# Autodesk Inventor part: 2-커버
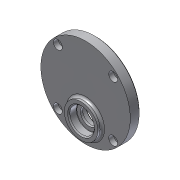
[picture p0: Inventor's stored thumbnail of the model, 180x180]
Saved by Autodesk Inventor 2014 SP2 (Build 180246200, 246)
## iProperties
Created: 2014-12
Part Number: 2-커버
Material: 알루미늄 6061
Document SubType Name: Modeling
Designer: 02
Density: 2.71 g/cm^3
Appearance: 알루미늄 - 평지
Mass: 113.832 g
Surface Area: 145.243 cm^2
Volume: 42.0044 cm^3
Author: 02
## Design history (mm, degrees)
sketch "스케치1"
  geometry: C1 r 40 at (0, 0); 1 further point
  constraints: 1 centre point, 1 coincident
  dimensions: "d0" = 80 diameter of C1
extrude "돌출1" new body sketch "스케치1" distance "d1" = 9; taper "d2" = 0 deg
sketch "스케치2"
  geometry: C1 r 40 at (0, 0) reference; C2 r 15 at (0, -20)
  constraints: 1 centre point, 1 vertical alignment
  dimensions: "d3" = 30 diameter of C2; "d4" = 20 distance of C2.centre C1.centre
extrude "돌출2" join sketch "스케치2" distance "d5" = 4; taper "d6" = 0 deg
sketch "스케치3"
  geometry: L1 (0, -20)-(0, 0); L2 (0, 0)-(0, 11); C1 r 40 at (0, 0) reference; C2 r 14 at (0, 11); C3 r 14 at (0, -20)
  constraints: 4 end point, 2 centre point, 1 collinear, 1 equal radius, 1 vertical
  dimensions: "d7" = 11 distance of L1.end L2.end; "d8" = 20 distance of L1.start L1.end; "d9" = 28 diameter of C2
extrude "돌출3" join sketch "스케치3" distance "d10" = 3; taper "d11" = 0 deg
sketch "스케치4"
  geometry: C1 r 14 at (0, 0) reference; C2 r 11 at (0, 0); 1 further point
  constraints: 1 centre point, 1 coincident
  dimensions: "d12" = 22 diameter of C2
extrude "돌출4" cut sketch "스케치4" distance "d13" = 7; taper "d14" = 0 deg
sketch "스케치5"
  geometry: C1 r 9 at (0, 0); 2 further points
  constraints: 1 centre point, 1 coincident, 1 vertical alignment
  dimensions: "d15" = 18 diameter of C1
extrude "돌출5" cut sketch "스케치5" distance "d16" = 1; taper "d17" = 0 deg
sketch "스케치6"
  geometry: C1 r 14 at (0, 0) reference; C2 r 11 at (0, 0); 1 further point
  constraints: 1 centre point, 1 coincident
  dimensions: "d18" = 22 diameter of C2
extrude "돌출6" cut sketch "스케치6" distance "d19" = 7; taper "d20" = 0 deg
sketch "스케치7"
  geometry: C1 r 15 at (0, 0) reference; C2 r 11 at (0, 0); 1 further point
  constraints: 1 centre point, 1 coincident
  dimensions: "d21" = 22 diameter of C2
extrude "돌출7" cut sketch "스케치7" distance "d22" = 7; taper "d23" = 0 deg
sketch "스케치8"
  geometry: C1 r 11 at (0, 0) reference; C2 r 7.5 at (0, 0); 1 further point
  constraints: 1 centre point, 1 coincident
  dimensions: "d24" = 15 diameter of C2
extrude "돌출8" cut sketch "스케치8" stored distance "d25" = 7; taper "d26" = 0 deg
sketch "스케치9"
  geometry: L1 (0, 0)-(0, 35); L2 (0, 0)-(24.749, 24.749); C1 r 40 at (0, 0) reference; A1 r 35 centre (0, 0) between (0, 35) and (24.749, 24.749)
  constraints: 4 end point, 2 point on circle, 1 centre point, 1 coincident, 1 vertical
  dimensions: "d27" = 70 diameter of A1; "d28" = 45 deg angle of L2 L1
hole "구멍1" sketch "스케치9" at (24.749, 24.749) diameter "d29" = 4.5; stored, may be unused: countersink angle "d33" = 90 deg, drill point angle "d35" = 118 deg; dims "d30" = 6, "d31" = 8, "d32" = 4.4, "d34" = 8
fillet "모깎기1" dims "d39" = 0.3
chamfer "모따기1" distance "d40" = 1; stored, may be unused: second distance "d41" = 2, angle "d42" = 45 deg
fillet "모깎기2" dims "d43" = 2
node "솔리드1"
pattern_circular "원형 패턴1" dims angle "d37" = 360 deg
